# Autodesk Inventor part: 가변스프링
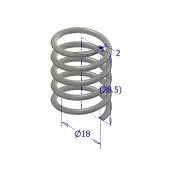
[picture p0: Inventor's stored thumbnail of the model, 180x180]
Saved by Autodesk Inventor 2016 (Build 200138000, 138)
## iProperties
Created: 2018-12
Part Number: 가변스프링
Material: 스테인레스 스틸
Document SubType Name: Modeling
Designer: 3sil_cad019
Density: 8 g/cm^3
Appearance: 반연마
Mass: 6.99701 g
Surface Area: 17.7559 cm^2
Volume: 0.874626 cm^3
Author: 3sil_cad019
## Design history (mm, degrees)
sketch "스케치1"
  geometry: L1 (0, 0)-(9, 0); L2 (9, 0)-(9, 28.5); L3 (9, 28.5)-(0, 28.5); L4 (0, 28.5)-(0, 0); C1 r 1 at (9, 0)
  constraints: 8 end point, 2 parallel, 1 centre point, 1 coincident, 1 horizontal, 1 perpendicular
  dimensions: "d0" = 2 diameter of C1; "d1" = 28.5 distance of L1.end L2.end (derived); "d2" = 18 diameter of L2 L4
feature "코일1" sketch "스케치1" pitch "d3" = 10; turns "d5" = 5; dims "d4" = 28.5 (= d1), "d6" = 0, angle "d7" = 90 deg, angle "d8" = 90 deg, "d9" = 0, "d10" = 0
node "작업 평면1"
sketch "스케치2"
  geometry: L1 (8, 0)-(10, 0) reference; 1 further point
  constraints: 1 horizontal alignment
extrude "돌출1" cut sketch "스케치2" distance "d12" = 10; taper "d13" = 0 deg
node "작업 평면2"
sketch "스케치3"
  geometry: L1 (1, 0)-(-1, 0) reference; 1 further point
  constraints: 1 horizontal alignment
extrude "돌출2" cut sketch "스케치3" distance "d15" = 10; taper "d16" = 0 deg
node "솔리드1"
node "절단 모서리 투영1"
node "절단 모서리 투영2"
other parameters: "d11" = 90 deg, "d14" = 90 deg
